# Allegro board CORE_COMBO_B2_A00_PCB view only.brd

Outline 277.73 x 153.4 mm; copper layers: TOP, GND1, IN1, VCC, IN2, IN3, GND2, IN4, GND3, BOTTOM. Coordinates in mm from the lower left corner of the outline.

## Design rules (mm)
net group CRYSTAL: nets PCH_RTCX2 PCH_RTCX2_R
net group DP_AUX_DC: nets DPB_AUX DPB_AUX# DPB_AUX#_C DPB_AUX_C
net group I2C: nets I2C0_SCL_VMM I2C0_SCL_VMM_R I2C0_SDA_VMM I2C0_SDA_VMM_R
net group PCBEEP: nets AUD_PC_BEEP PC_SPKR SPKR
net group PCIE: nets PCIE_PTX_C_DRX_N10 PCIE_PTX_C_DRX_P10 PCIE_PTX_DRX_N10 PCIE_PTX_DRX_P10
net group SMBUS: nets PBAT_SMBCLK PBAT_SMBCLK_C PBAT_SMBDAT PBAT_SMBDAT_C
net group UART: nets ISH_UART0_CTS# ISH_UART0_CTS#_R ISH_UART0_RTS# ISH_UART0_RTS#_R ISH_UART0_RXD ISH_UART0_RXD_R ISH_UART0_TXD ISH_UART0_TXD_R

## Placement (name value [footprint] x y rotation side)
C4  -  [C0402]  151.34 138.72 180 bottom
C7  -  [C1210]  71.18 82.33 270 bottom
C8  -  [C0603]  149.77 137.66 90 bottom
C9  -  [C0402]  83.63 145.02 180 top
C10  -  [NB_C0402_SMALL]  72.02 143.81 180 bottom
C11  -  [NB_C0402_SMALL]  74.56 142.08 180 bottom
C12  -  [NB_C0402_SMALL]  77.96 140.83 0 bottom
C13  -  [NB_C0402_SMALL]  73.71 146.17 270 bottom
C14  -  [NB_C0402_SMALL]  76.25 144.27 270 bottom
C15  -  [NB_C0402_SMALL]  78.85 142.95 270 bottom
C16  -  [NB_C0402_SMALL]  84.49 145.78 180 bottom
C17  -  [NB_C0402_SMALL]  91.32 144.62 90 bottom
C18  -  [NB_C0402_SMALL]  86.8 144.62 90 bottom
C19  -  [C0402]  85.91 140.7 90 top
C20  -  [C0402]  84.9 140.7 90 top
C21  -  [C0402]  88.86 124.91 180 bottom
C22  -  [C0402]  86.46 127.39 0 bottom
C23  -  [VX_C0402_SMALL]  89.19 133.69 90 bottom
C24  -  [VX_C0402_SMALL]  85.07 127.64 90 bottom
C25  -  [C0402]  90.13 133.72 90 bottom
C26  -  [C0402]  83.28 126 270 bottom
C27  -  [C0402]  84.54 125.34 270 bottom
C28  -  [VX_C0402_SMALL]  91.55 130.8 270 bottom
C29  -  [VX_C0402_SMALL]  84.25 127.09 90 bottom
C34  -  [C0402]  76.64 146.42 0 top
C42  -  [NB_C0402_SMALL]  80.2 136.13 90 top
C43  -  [NB_C0402_SMALL]  80.2 134.48 270 top
C50  -  [C0402]  75.25 24.5 270 top
C52  -  [C0603]  54.03 108.99 0 top
C54  -  [C0402]  42.48 96.89 90 bottom
C55  -  [C0402]  43.5 96.89 90 bottom
C56  -  [C0402]  45.65 96.89 90 bottom
C57  -  [C0402]  48.02 98.16 90 bottom
C59  -  [C0402]  44.64 96.89 90 bottom
C60  -  [C0402]  47 98.16 90 bottom
C61  -  [C0402]  40.96 109.85 0 top
C62  -  [C0402]  42.99 104.13 90 top
C63  -  [C0402]  53.4 98.06 180 bottom
C64  -  [C0402]  37.91 102.1 90 top
C65  -  [C0603]  54.03 110.29 0 top
C66  -  [NB_C0402_SMALL]  44.08 108.71 270 top
C68  -  [C0402]  35.24 102.48 180 top
C76  -  [C0402]  155.38 123.18 0 bottom
C85  -  [C0402]  144.21 118.99 0 bottom
C87  -  [C0402]  16.07 119.24 0 bottom
C88  -  [C0603]  15.68 121.28 90 bottom
C103  -  [C0402]  21.27 114.42 0 top
C111  -  [NB_C0402_SMALL]  153.86 61.41 180 bottom
C112  -  [C0402]  153.86 62.42 180 bottom
C113  -  [C0402]  153.1 57.06 180 bottom
C114  -  [C0402]  153.1 58.13 180 bottom
C115  -  [C0402]  38.42 125.59 180 bottom
C117  -  [C0402]  148.17 128.13 0 top
C118  -  [C0603]  45.02 125.64 180 bottom
C119  -  [C0402]  44.97 122.44 180 bottom
C120  -  [C0402]  44.89 124.42 180 bottom
C122  -  [C0603]  48.32 118.1 270 bottom
C123  -  [C0402]  47.05 118.1 270 bottom
C124  -  [NB_C0402_SMALL]  35.12 97.4 90 top
C125  -  [NB_C0402_SMALL]  35.12 94.73 270 top
C128  -  [C0603]  44.51 117.84 270 bottom
C129  -  [C0402]  45.78 118.1 270 bottom
C131  -  [C0603]  36.31 128.4 180 top
C133  -  [C0402]  47.2 125.59 0 top
C134  -  [C0402]  35.62 118.48 180 top
C135  -  [C0402]  51.5 121.53 180 top
C136  -  [NB_C0402_SMALL]  51.5 122.8 180 top
C137  -  [C0402]  34.44 131.18 180 bottom
C139  -  [NB_C0402_SMALL]  48.83 120.64 180 top
C143  -  [C0402]  47.2 126.73 0 top
C147  -  [NB_C0402_SMALL]  47.98 130.52 0 bottom
C148  -  [NB_C0402_SMALL]  47.98 129.38 0 bottom
C149  -  [C0402]  50.07 126.66 0 bottom
C150  -  [C0603]  37.76 120.1 180 bottom
C151  -  [C0402]  50.76 131.89 0 bottom
C155  -  [C0402]  87.98 140.3 90 top
C156  -  [C0402]  86.96 140.3 90 top
C157  -  [C0402]  89.22 138.29 90 top
C158  -  [C0402]  88.2 138.29 90 top
C159  -  [C0402]  91.59 138.29 90 top
C160  -  [C0402]  90.57 138.29 90 top
C161  -  [C0402]  94.49 137.62 0 top
C162  -  [C0402]  94.49 136.6 0 top
C176  -  [C0402]  139.36 134.05 180 top
C178  -  [C0402]  139.36 132.91 180 top
C179  -  [C0402]  139.36 135.07 180 top
C180  -  [C0603]  139.25 129.78 180 top
C181  -  [C0402]  139.36 131.89 180 top
C182  -  [C0402]  145.48 132.7 180 bottom
C183  -  [C0402]  147.76 134.23 180 bottom
C184  -  [C0402]  142.17 133.59 180 bottom
C185  -  [C0402]  142.17 134.74 180 bottom
C186  -  [C0402]  144.08 134.74 0 bottom
C187  -  [C0805]  140.65 137.76 180 top
C188  -  [C0805]  149.29 131.06 90 bottom
C189  -  [C0402]  144.46 125.72 0 top
C190  -  [C0402]  146.72 125.77 0 top
C191  -  [C0402]  21.27 115.56 0 top
C198  -  [C0402]  162.39 139.08 270 top
C199  -  [C0402]  21.27 117.08 0 top
C208  -  [C0402]  174.41 34.81 270 bottom
C209  -  [C0402]  21.27 118.23 0 top
C242  -  [C0402]  22.29 128 0 bottom
C243  -  [C0402]  22.29 129.02 0 bottom
C248  -  [NB_C0402_SMALL]  99.05 121.48 270 bottom
C249  -  [NB_C0402_SMALL]  99.12 141.09 90 bottom
C250  -  [C0402]  98.03 121.48 270 bottom
C251  -  [C0805]  98.62 137.15 270 bottom
C252  -  [C0402]  96.33 141.09 90 bottom
C253  -  [C7343D_H75]  92.52 121.78 0 bottom
C254  -  [C7343D_H75]  92.64 137.63 0 bottom
C257  -  [C0402]  31.18 114.93 180 bottom
C258  -  [NB_C0402_SMALL]  31.18 116.07 180 bottom
C259  -  [NB_C0402_SMALL]  31.94 135.88 0 top
C260  -  [C0402]  31.94 133.72 0 top
C261  -  [C0402]  31.94 134.86 0 top
C262  -  [C0603]  33.59 114.93 0 bottom
C263  -  [C0402]  15.17 140.83 0 top
C266  -  [C0402]  13.65 138.55 0 top
C269  -  [C0402]  21.27 111.88 0 top
C270  -  [C0402]  21.27 113.02 0 top
C271  -  [C0402]  21.27 109.46 0 top
C272  -  [C0402]  21.27 110.61 0 top
C288  -  [C0603]  27.93 97.71 90 top
C289  -  [C0402]  26.74 97.91 90 top
C290  -  [C7343D_H75]  21.52 100.45 180 top
C291  -  [C0402]  17.59 97.4 0 top
C292  -  [C0402]  24.88 95.7 0 top
C293  -  [C0402]  24.88 96.71 0 top
C328  -  [C0603]  271.54 51.5 0 top
C329  -  [C0402]  268.29 55.23 0 top
C330  -  [C0402]  252.39 53.71 180 top
C331  -  [C0402]  256.47 45.58 270 top
C332  -  [C0402]  259.01 61.84 90 top
C333  -  [C0402]  17.84 125.09 180 bottom
C334  -  [C0402]  267.52 48.76 270 top
C336  -  [C0603]  257.74 62.22 90 top
C337  -  [NB_C0402_SMALL]  252.54 58.28 180 top
C339  -  [C0402]  270.19 54.09 0 top
C340  -  [C0402]  225.88 47.42 270 top
C342  -  [C0402]  224.85 47.74 90 top
C343  -  [C0402]  227.62 49.24 0 top
C344  -  [C0402]  225.88 49.95 270 top
C345  -  [C0402]  222.13 51.35 0 top
C346  -  [C0402]  242.05 55.77 0 top
C347  -  [C0402]  222.69 58.61 180 top
C348  -  [C0603]  241.29 68.31 90 top
C349  -  [C0402]  232.98 64.39 90 top
C350  -  [C0402]  241.87 63.36 0 top
C351  -  [C0402]  242 58.03 0 top
C352  -  [C0402]  242.05 54.62 0 top
C353  -  [C0402]  225.11 57.52 180 top
C354  -  [C0402]  229.65 49.24 180 top
C355  -  [C0402]  241.23 48.3 0 top
C356  -  [C0402]  225.23 60.44 180 top
C358  -  [NB_C0402_SMALL]  239.58 49.26 0 top
C359  -  [NB_C0402_SMALL]  241.23 49.26 0 top
C360  -  [C0402]  226.5 62.85 180 top
C361  -  [NB_C0402_SMALL]  240.47 51.93 270 top
C362  -  [C0402]  231.71 64.39 90 top
C363  -  [NB_C0402_SMALL]  245.04 60.31 0 top
C364  -  [C0402]  226.25 53.96 90 top
C365  -  [C0402]  226.25 51.93 270 top
C366  -  [C0603]  244.71 53.71 0 top
C367  -  [C0402]  241.84 52.11 0 top
C368  -  [NB_C0402_SMALL]  245.68 37.45 90 top
C369  -  [NB_C0402_SMALL]  243.52 48.93 270 top
C370  -  [NB_C0402_SMALL]  156.4 106.03 90 bottom
C371  -  [C0402]  242.12 61.33 270 top
C373  -  [NB_C0402_SMALL]  199.5 25.21 90 bottom
C374  -  [C0402]  144.33 63.91 0 top
C375  -  [C0402]  144.46 51.14 180 top
C376  -  [C0402]  144.46 50.03 180 top
C377  -  [NB_C0402_SMALL]  150.38 61.2 270 top
C378  -  [NB_C0402_SMALL]  150.38 64.12 90 top
C379  -  [NB_C0402_SMALL]  148.22 62.04 270 top
C380  -  [NB_C0402_SMALL]  148.22 63.69 90 top
C385  -  [C0603]  38.39 122.62 90 bottom
C389  -  [C0402]  182.43 89.9 180 top
C390  -  [NB_C0402_SMALL]  181.67 90.92 180 top
C391  -  [NB_C0402_SMALL]  181.54 97.91 180 top
C393  -  [C0402]  182.43 98.92 0 top
C395  -  [NB_C0402_SMALL]  227.32 64.5 270 top
C396  -  [C0402]  182.43 95.87 180 top
C397  -  [NB_C0402_SMALL]  181.54 97.02 180 top
C398  -  [NB_C0402_SMALL]  207.22 64.12 90 top
C399  -  [C0402]  206.03 63.46 270 top
C400  -  [C0402]  181.87 85.76 0 top
C401  -  [NB_C0402_SMALL]  181.67 87.62 180 top
C402  -  [NB_C0402_SMALL]  208.11 64.12 90 top
C403  -  [C0402]  209.1 63.36 270 top
C409  -  [NB_C0402_SMALL]  54.47 117.92 180 bottom
C410  -  [C0402]  44.97 117.49 270 top
C413  -  [NB_C0402_SMALL]  199.58 40.63 90 bottom
C422  -  [C0402]  53.78 120.51 90 bottom
C425  -  [C0402]  58.1 117.97 90 bottom
C426  -  [C0402]  184.47 136.01 270 top
C427  -  [NB_C0402_SMALL]  55.94 117.72 270 bottom
C430  -  [C0402]  199.07 39.28 0 bottom
C431  -  [NB_C0603_H34_SMALL]  53.53 96.87 0 bottom
C440  -  [C0402]  36.38 109.84 180 top
C452  -  [C0402]  184.47 138.93 90 top
C633  -  [C0402]  187.77 54.98 270 bottom
C634  -  [C0402]  189.29 54.98 270 bottom
C635  -  [C0402]  186.62 54.98 270 bottom
C645  -  [C0402]  194.78 56.71 90 bottom
C647  -  [C0402]  171.26 57.01 180 bottom
C648  -  [C0402]  171.26 56 180 bottom
C809  -  [C7343D_H75]  21.52 100.83 180 bottom
C1002  -  [C0402]  259.27 5.2 90 top
C1103  -  [C0402]  137.43 110.13 270 top
C1104  -  [C0402]  136.41 110.13 270 top
C1186  -  [C0402]  181.47 106.97 0 top
C1187  -  [C0402]  258.89 8.88 90 top
C1189  -  [C0402]  115.63 65.14 180 top
C2750  -  [NB_C0402_SMALL]  51.5 123.76 0 top
C2800  -  [C0402]  164.63 125.32 180 bottom
C2801  -  [C0402]  164.63 124.3 180 bottom
C2802  -  [C0402]  168.26 122.8 180 top
C2803  -  [C0402]  164.63 123.27 180 bottom
C2805  -  [C1808]  164.12 129.39 90 bottom
C3004  -  [NB_C0402_SMALL]  199.1 36.64 0 bottom
C3005  -  [C0402]  199.07 38.24 0 bottom
C3050  -  [C0402]  185.86 128.89 90 top
C3051  -  [C0402]  184.47 133.47 270 top
C3052  -  [C0603]  184.47 129.15 90 top
C3053  -  [C0603]  182.05 121.02 270 top
C3054  -  [C0402]  182.69 125.97 180 top
C3055  -  [C0402]  182.81 131.18 0 top
C3056  -  [C0402]  187.01 131.18 180 top
C3057  -  [C0402]  182.56 133.34 270 top
C3058  -  [C0402]  185.61 133.47 270 top
C3059  -  [C0402]  186.24 136.39 90 bottom
C3060  -  [C0402]  185.1 136.39 90 bottom
C3061  -  [C0402]  181.98 122.8 180 bottom
C3062  -  [C0402]  181.98 124.98 180 bottom
C3063  -  [C0402]  189.29 129.02 270 bottom
C3079  -  [C0402]  175.45 54.6 0 top
C3080  -  [NB_C3528_H79]  152.26 134.48 90 bottom
C3082  -  [C0402]  181.42 103.62 0 top
C3083  -  [C0402]  181.14 129.53 270 top
C3084  -  [VX_C0402_SMALL]  86.8 125.95 180 bottom
C3085  -  [C0402]  89.22 127.46 270 bottom
C3086  -  [C0402]  86.5 130.01 180 bottom
C3087  -  [C0402]  91.17 133.72 90 bottom
C3088  -  [VX_C0402_SMALL]  84.39 130.93 90 bottom
C3091  -  [VX_C0402_SMALL]  84.39 129.27 270 bottom
C3092  -  [C0402]  83.37 129.15 270 bottom
C3093  -  [VX_C0402_SMALL]  86.42 128.71 180 bottom
C3094  -  [VX_C0402_SMALL]  89.57 130.27 90 bottom
C3401  -  [C0603]  139 137.66 90 bottom
C3402  -  [C0402]  140.27 137.78 90 bottom
C3601  -  [C0402]  205.3 150.36 90 top
C3602  -  [C0402]  207.84 148.33 180 top
C3603  -  [C0402]  211.01 141.47 180 top
C3701  -  [C0402]  263.41 39.64 90 top
C7106  -  [NB_C0402_SMALL]  245.27 99.43 0 bottom
C7108  -  [NB_C0402_SMALL]  240.35 105.07 180 bottom
C7109  -  [NB_C0402_SMALL]  240.93 107.61 180 bottom
C7110  -  [NB_C0402_SMALL]  244.13 111.36 270 bottom
C7111  -  [NB_C0402_SMALL]  248.47 110.5 90 bottom
C7112  -  [NB_C0402_SMALL]  245.27 98.36 0 bottom
C9207  -  [C0402]  174.71 42.81 0 bottom
C9430  -  [NB_R0402_SMALL]  49.09 93.89 90 bottom
C9432  -  [C0603]  38.42 127.11 180 bottom
C9433  -  [VX_C0402_SMALL]  265.87 39.26 180 top
C9437  -  [C0402]  261.28 41.95 180 top
C9438  -  [C0603]  137.4 138.19 90 bottom
C9439  -  [C0603]  136.08 138.19 90 bottom
C9440  -  [C0603]  128.31 134.71 180 bottom
C9441  -  [C0402]  118.81 146.93 90 bottom
C9442  -  [C0402]  122.24 146.93 90 bottom
C9443  -  [C0402]  119.95 146.93 90 bottom
C9444  -  [C0402]  121.09 146.93 90 bottom
C9445  -  [C0402]  259.65 26.66 180 top
C9446  -  [C0402]  259.65 25.52 180 top
C9447  -  [C0402]  262.37 39.64 90 top
C9448  -  [C0402]  270.7 34.53 0 top
C9449  -  [C0402]  270.57 31.87 0 top
C9450  -  [C0402]  257.24 30.98 270 top
C9451  -  [C0402]  261.33 39.64 90 top
C9453  -  [C0603]  133.16 143.12 0 top
C9454  -  [C0603]  130.11 146.17 0 top
C9455  -  [NB_C0402_SMALL]  132.14 137.78 90 top
C9456  -  [C0603]  134.02 138.29 0 top
C9457  -  [C0402]  153.45 103.26 270 bottom
C9458  -  [C0402]  155.26 102.86 180 bottom
C9459  -  [C0402]  155.13 98.29 180 bottom
C9460  -  [NB_C0402_SMALL]  237.93 49.26 180 top
C9461  -  [NB_C0402_SMALL]  157.67 68.19 90 bottom
C9462  -  [C0402]  159.07 129.78 180 bottom
C9463  -  [C0402]  193.74 56.71 90 bottom
C9464  -  [C0402]  117.66 146.93 90 bottom
C9491  -  [C0402]  244.41 59.3 180 top
C9492  -  [NB_C0402_SMALL]  175.42 34.97 90 bottom
C9493  -  [NB_C0402_SMALL]  175.58 49.39 0 top
C9494  -  [NB_C0402_SMALL]  175.58 51.68 0 top
C9495  -  [NB_C0402_SMALL]  175.58 52.57 0 top
C9505  -  [NB_C0402_SMALL]  183.07 137.53 270 top
C9506  -  [NB_C0402_SMALL]  159.19 129.27 180 top
C9507  -  [NB_C0402_SMALL]  161.86 136.51 90 top
C9508  -  [NB_C0402_SMALL]  35.37 100.57 0 top
C9509  -  [NB_C0402_SMALL]  43.24 101.46 0 top
C9510  -  [NB_C0402_SMALL]  54.16 107.09 0 top
C9511  -  [NB_C0402_SMALL]  53.58 99 180 bottom
C9512  -  [NB_C0402_SMALL]  41.09 101.46 0 top
C9513  -  [NB_C0402_SMALL]  12.89 141.09 90 top
C9514  -  [NB_C0402_SMALL]  13.78 141.09 90 top
C9515  -  [C0402]  40.96 130.57 270 top
C9516  -  [C0402]  39.38 130.8 270 top
C9525  -  [C0402]  15.3 115.31 270 bottom
C9526  -  [C0402]  16.45 115.31 270 bottom
C9527  -  [C0402]  16.42 117.72 270 bottom
C9528  -  [C0402]  15.3 117.72 270 bottom
C9539  -  [NB_C0402_SMALL]  94.96 110.2 90 bottom
C9540  -  [NB_C0402_SMALL]  92.37 110.2 90 bottom
C9541  -  [NB_C0402_SMALL]  89.88 110.2 90 bottom
C9542  -  [NB_C0402_SMALL]  94.07 110.2 270 bottom
C9543  -  [NB_C0402_SMALL]  93.2 110.2 270 bottom
C9544  -  [NB_C0402_SMALL]  90.71 110.2 270 bottom
C9548  -  [C0402]  130.31 109.72 270 bottom
C9549  -  [C0402]  131.38 109.72 270 bottom
C9550  -  [C0402]  132.14 115.43 270 bottom
C9551  -  [C0402]  131 115.43 270 bottom
C9552  -  [C0402]  163.23 53.2 180 top
C9553  -  [VX_C0402_SMALL]  169.05 48.78 90 top
C9554  -  [VX_C0402_SMALL]  167.57 61.53 180 top
C9555  -  [C0402]  163.16 64.17 180 top
C9556  -  [C0402]  181.42 101.46 0 top
C9557  -  [C0402]  181.42 102.53 0 top
C9558  -  [C0603]  181.44 104.82 0 top
C9559  -  [C0402]  159.37 122.09 90 bottom
C9560  -  [C0402]  152.33 118.73 270 bottom
C9562  -  [C0402]  187.67 149.7 90 bottom
C9563  -  [C0603]  188.93 149.99 90 bottom
C9564  -  [C0402]  187.23 141.24 270 bottom
C9565  -  [C0603]  194.93 143.07 0 bottom
C9566  -  [C0402]  194.75 144.26 0 bottom
C9567  -  [C0402]  192.21 149.98 90 bottom
C9568  -  [C0402]  193.76 47.61 270 bottom
C9569  -  [C0603]  194.98 47.71 270 bottom
C9606  -  [C0603]  120.33 70.6 270 top
C9607  -  [C0402]  121.52 70.45 270 top
C9608  -  [C0402]  122.75 110.04 270 bottom
C9609  -  [C0402]  123.77 112.3 90 bottom
C9610  -  [C0402]  115.89 68.39 180 top
C9611  -  [C0402]  122.75 111.94 90 bottom
C9612  -  [C0402]  117.71 73.75 270 top
C9613  -  [C0603]  107.5 72.79 180 top
C9614  -  [C0603]  107.5 74.11 180 top
C9615  -  [C0402]  107.5 71.26 180 top
C9616  -  [C0402]  115.28 74.69 0 top
C9617  -  [C0402]  118.86 73.75 270 top
C9618  -  [C0603]  115.17 73.52 0 top
C9619  -  [C0805]  94.42 50.28 180 top
C9620  -  [C0603]  115.17 72.22 0 top
C9621  -  [C0603]  115.17 70.9 0 top
C9622  -  [C0603]  115.17 69.58 0 top
C9623  -  [C0805]  96.84 76.44 0 top
C9624  -  [C0805]  95.82 53.46 180 top
C9625  -  [C0402]  127.57 90.11 0 top
C9626  -  [C0402]  124.27 92.83 180 top
C9627  -  [C0402]  137.81 88.86 90 top
C9628  -  [C0402]  142.61 110.25 90 bottom
C9629  -  [C0805]  153.81 110.45 270 top
C9630  -  [C0402]  155.36 110.94 270 top
C9631  -  [C0402]  131.89 98.03 90 top
C9632  -  [C0805]  153.6 107.35 180 top
C9633  -  [C0402]  129.22 95.24 180 top
C9634  -  [C0402]  125.03 91.78 180 top
C9635  -  [C0402]  124.27 93.85 180 top
C9636  -  [C0402]  126.3 95.87 180 top
C9637  -  [C0402]  127.57 92.7 0 top
C9638  -  [C0402]  131.71 88.63 270 top
C9639  -  [C0402]  129.45 90.11 180 top
C9640  -  [C0402]  137.98 97.27 0 top
C9641  -  [C0402]  143.83 91.63 0 bottom
C9642  -  [C0402]  134.02 68.21 270 top
C9643  -  [C0402]  132.98 68.21 270 top
C9644  -  [C0402]  130.11 76.19 180 top
C9645  -  [C0402]  130.11 75.05 180 top
C9647  -  [C0805]  146.39 111.37 270 top
C9648  -  [C0805]  142.31 111.37 270 top
C9649  -  [C0805]  144.35 111.37 270 top
C9650  -  [C0402]  133.08 109.39 270 bottom
C9653  -  [C0402]  157.39 101.08 90 top
C9654  -  [C0603]  154.96 97.04 90 top
C9655  -  [C0603]  157.02 96.41 0 top
C9656  -  [C0805]  140.27 111.37 270 top
C9657  -  [C0402]  122.74 88.53 0 top
C9658  -  [C0402]  120.86 89.57 180 top
C9659  -  [C0402]  120.86 88.53 180 top
C9660  -  [C0402]  113.02 90.49 180 top
C9663  -  [C0402]  113.02 89.42 180 top
C9664  -  [C0402]  113.02 88.38 180 top
C9665  -  [C0402]  122.74 89.57 0 top
C9666  -  [C0402]  122.62 91.05 90 top
C9840  -  [NB_C0402_SMALL]  181.67 86.73 180 top
C9841  -  [NB_C0402_SMALL]  181.67 91.81 180 top
C9842  -  [C0402]  182.74 88.84 0 top
C9843  -  [C0402]  182.43 92.95 0 top
C9851  -  [C0402]  93.35 111.11 270 top
C9855  -  [C0402]  135.38 141.84 0 top
C9856  -  [C0402]  83.37 131.05 90 bottom
C9884  -  [C0402]  139.89 75.43 90 bottom
C9885  -  [C0402]  174.13 122.77 270 top
C9886  -  [C0402]  172.38 65.9 180 top
C9887  -  [C0402]  135.93 109.51 90 bottom
C9888  -  [C0603]  111.39 89.14 90 top
C9889  -  [C0603]  110.11 89.14 90 top
C9897  -  [C0603]  38.21 131.28 90 top
C9898  -  [C0603]  36.64 118.4 180 bottom
C9899  -  [C0603]  46.55 122.42 90 top
C9900  -  [C0402]  35.62 119.62 180 top
C9901  -  [C0603]  35.93 126.58 180 top
C9903  -  [C0402]  38.01 118.43 180 top
C9904  -  [C0603]  37.96 116.98 180 bottom
C9905  -  [C0402]  181.11 109.51 0 top
C9906  -  [C0402]  94.73 119.14 90 top
C9907  -  [NB_C0402_SMALL]  43.24 102.35 0 top
C9908  -  [NB_C0402_SMALL]  35.37 101.46 180 top
C9909  -  [NB_C0402_SMALL]  53.91 99.94 180 bottom
C9910  -  [NB_C0402_SMALL]  54.16 107.93 0 top
C9911  -  [NB_C0402_SMALL]  41.09 102.35 0 top
C9912  -  [NB_C0402_SMALL]  55.81 98.67 270 bottom
C9913  -  [NB_C0402_SMALL]  83.63 145.99 180 top
C9914  -  [NB_C0402_SMALL]  82.23 135.73 90 bottom
C9915  -  [NB_C0402_SMALL]  82.1 130.67 180 top
C9916  -  [NB_C0402_SMALL]  82.1 129.3 180 top
C9917  -  [NB_C0402_SMALL]  82.1 128.26 180 top
C9918  -  [C0402]  162.85 120.66 0 bottom
C9919  -  [C0402]  171.03 42.53 90 bottom
C9920  -  [C0402]  172.65 42.79 180 bottom
C9921  -  [C0402]  170.75 35.19 0 bottom
C9922  -  [C0402]  173.26 34.81 270 bottom
C9923  -  [NB_C0402_SMALL]  183.07 135.88 270 top
C9924  -  [NB_C0402_SMALL]  193.64 141.29 270 bottom
C9925  -  [NB_C0402_SMALL]  181.42 105.93 0 top
C9926  -  [NB_C0402_SMALL]  175.58 53.46 0 top
C9927  -  [NB_C0402_SMALL]  181.16 108.55 0 top
C9928  -  [NB_C0402_SMALL]  181.47 100.47 0 top
C9929  -  [C0402]  73.59 30.09 180 top
C9930  -  [C0603]  153.55 73.65 180 bottom
C9931  -  [C0402]  155.26 101.79 180 bottom
C9941  -  [NB_C0402_SMALL]  259.14 39.46 90 top
C9942  -  [C0402]  145.48 131.56 180 bottom
C9943  -  [C0402]  86.17 134.02 180 bottom
C9944  -  [VX_C0402_SMALL]  87.92 133.9 0 bottom
C9945  -  [VX_C0402_SMALL]  87.92 134.74 0 bottom
C9946  -  [C0402]  86.17 135.12 180 bottom
C9947  -  [C0402]  86.93 124.93 180 bottom
C9948  -  [C0402]  155.27 91.63 180 bottom
C9949  -  [C0402]  155.27 90.62 180 bottom
C9950  -  [C0402]  88.58 114.29 0 top
C9952  -  [C0603]  148.4 137.66 90 bottom
C9953  -  [C0402]  269.23 45.28 0 top
C9954  -  [C0402]  271.41 46.11 90 top
C9955  -  [C0402]  272.55 37.2 270 top
C9956  -  [C0603]  269.34 46.44 0 top
C9957  -  [C0402]  272.35 49.01 0 top
C9958  -  [C0603]  138.67 75.36 90 bottom
C9959  -  [C0402]  129.73 92.7 180 top
C9960  -  [C0402]  127.39 88.58 0 top
C9961  -  [NB_C0402_SMALL]  161.22 111.62 270 top
C9962  -  [C0402]  162.37 111.62 270 top
C9963  -  [NB_C0402_SMALL]  130.69 127.32 270 bottom
C9964  -  [NB_C0402_SMALL]  131.61 127.32 270 bottom
C9965  -  [NB_C0402_SMALL]  188.4 28.74 270 top
C9966  -  [C0402]  189.42 28.82 270 top
C9967  -  [NB_C0402_SMALL]  185.1 85.1 180 top
C9968  -  [C0402]  190.76 84.82 0 top
C9969  -  [NB_C0402_SMALL]  74.36 89.4 270 bottom
C9970  -  [C0402]  76.01 89.27 270 bottom
C9971  -  [NB_C0402_SMALL]  69.66 85.71 0 bottom
C9972  -  [C0402]  69.66 87.24 0 bottom
C9973  -  [NB_C0402_SMALL]  107.53 122.19 180 top
C9974  -  [C0402]  107.53 123.18 180 top
C9975  -  [NB_C0402_SMALL]  118.37 116.42 0 bottom
C9976  -  [C0402]  118.4 117.67 0 bottom
C9977  -  [NB_C0402_SMALL]  114.74 128.13 270 bottom
C9978  -  [C0402]  117.66 128.26 270 bottom
C9979  -  [NB_C0402_SMALL]  98.23 141.09 90 bottom
C9980  -  [NB_C0402_SMALL]  97.34 141.09 90 bottom
C9981  -  [C0603]  193.69 149.92 90 bottom
C9982  -  [C0402]  249.26 47.54 90 top
C9983  -  [C0402]  121.96 65.93 270 top
C9984  -  [C0402]  115.9 67.35 180 top
C9985  -  [C0402]  123.12 64.45 180 top
C9986  -  [NB_C0402_SMALL]  50.86 97.15 270 bottom
CC5  -  [C0402]  130.9 66.87 90 top
CC6  -  [NB_C0402_SMALL]  120.23 110.5 0 bottom
CC7  -  [NB_C0402_SMALL]  117.94 110.5 180 bottom
CC10  -  [C0402]  79.36 114.49 180 bottom
CC11  -  [C0402]  79.36 113.45 180 bottom
CC24  -  [C0402]  132.8 88.63 90 top
CC25  -  [C0402]  130.67 71.31 90 top
CC26  -  [C0402]  135.82 88.63 0 top
CC41  -  [C0402]  60.89 115.74 180 bottom
CC57  -  [C0402]  126.05 70.85 180 top
CC67  -  [C0402]  132.65 39.11 0 top
CC69  -  [C0402]  133.67 25.77 0 top
CC80  -  [C0402]  128.71 71.24 90 top
CC89  -  [NB_C0402_SMALL]  184.41 125.21 180 bottom
CC90  -  [NB_C0402_SMALL]  186.19 125.21 0 bottom
CC91  -  [NB_C0402_SMALL]  144.11 76.01 0 bottom
CC92  -  [NB_C0402_SMALL]  145.22 74.44 0 bottom
CC93  -  [C0402]  82.74 114.29 270 bottom
CC94  -  [C0402]  157.67 89.14 90 top
CC266  -  [VX_C0402_SMALL]  157.26 92.7 90 top
CC267  -  [C0402]  133.67 75.17 270 bottom
CC268  -  [C0402]  79.92 125.51 0 bottom
CC269  -  [C0402]  131.79 92.52 0 top
CC270  -  [NB_C0402_SMALL]  90.99 102.22 0 bottom
CC271  -  [NB_C0402_SMALL]  93.03 103.11 0 bottom
CC272  -  [C0402]  75.37 127.12 270 bottom
CC273  -  [C0402]  81.67 114.29 270 bottom
CC275  -  [NB_C0402_SMALL]  153.38 94.98 180 bottom
CC276  -  [NB_C0402_SMALL]  138.82 111.49 180 bottom
CC277  -  [NB_C0402_SMALL]  129.09 76.01 270 bottom
CC278  -  [NB_C0402_SMALL]  138.74 111.11 90 top
CC279  -  [NB_C0402_SMALL]  125.28 73.52 90 top
CC280  -  [NB_C0402_SMALL]  128.2 76.01 270 bottom
CC281  -  [NB_C0402_SMALL]  252.41 52.69 0 top
CC282  -  [NB_C0402_SMALL]  255.46 45.71 90 top
CC284  -  [NB_C0402_SMALL]  244.41 56 180 top
CC285  -  [NB_C0402_SMALL]  238.44 67.17 90 top
CC286  -  [NB_C0402_SMALL]  230.77 64.5 270 top
CC287  -  [C0402]  130.9 64.71 90 top
CC288  -  [NB_C0402_SMALL]  137.04 109.36 270 bottom
CC289  -  [C0402]  130.67 69.33 90 top
CC290  -  [C0402]  127.57 71.24 90 top
CD3  -  [C0402]  106.61 39.1 180 top
CD4  -  [C0402]  110.3 47.23 90 top
CD5  -  [C0402]  123.25 47.23 90 top
CD6  -  [C0402]  119.94 47.23 90 top
CD7  -  [C0402]  122.11 47.23 90 top
CD8  -  [C0402]  113.85 47.23 90 top
CD9  -  [C0402]  98.23 38.49 270 top
CD10  -  [C0402]  120.97 47.23 90 top
CD11  -  [C0402]  112.71 47.23 90 top
CD12  -  [C0603]  127.96 38.48 270 top
CD13  -  [C0402]  126.81 38.48 270 top
CD14  -  [C0603]  120.71 38.47 270 top
CD15  -  [C0603]  112.37 38.34 270 top
CD16  -  [C0603]  116.39 38.47 270 top
CD17  -  [C0603]  113.67 38.34 270 top
CD18  -  [C0603]  122.11 38.47 270 top
CD19  -  [C0603]  111.04 38.34 270 top
CD20  -  [C0603]  117.92 38.47 270 top
CD21  -  [C0603]  109.72 38.34 270 top
CD22  -  [VX_C7343D_H79]  96.07 59.17 90 top
CD23  -  [C0402]  83.5 33.26 90 top
CD24  -  [C0402]  145.35 46.9 270 top
CD25  -  [C0603]  143.57 38.98 0 top
CD26  -  [C0402]  146.8 40.89 90 top
CD27  -  [C0402]  145.73 40.89 90 top
CD28  -  [C0402]  147.83 40.89 90 top
CD29  -  [C0402]  144.71 40.89 90 top
CD30  -  [C0603]  146.37 38.47 270 top
CD31  -  [C0603]  147.76 38.47 270 top
CD34  -  [C0402]  106.74 26.4 270 top
CD36  -  [C0402]  104.46 26.66 270 top
CD37  -  [C0402]  115.25 25.01 270 top
CD38  -  [C0402]  84.92 25.75 0 top
CD39  -  [C0402]  121.25 25.26 270 top
CD40  -  [C0402]  113.98 33.68 90 top
CD41  -  [C0402]  116.93 47.23 90 top
CD42  -  [C0402]  110.93 33.64 90 top
CD43  -  [C0402]  137.7 25.29 270 top
CD45  -  [C0603]  109.03 25.14 270 top
CD46  -  [C0603]  115.38 33.64 90 top
CD47  -  [C0603]  119.62 33.66 90 top
CD48  -  [C0603]  110.47 25.13 270 top
CD49  -  [C0603]  116.52 25.14 270 top
CD50  -  [C0603]  112.46 33.64 90 top
CD51  -  [C0603]  122.9 33.66 90 top
CD52  -  [C0603]  120.08 25.14 270 top
CD53  -  [VX_C7343D_H79]  129.09 33.79 180 top
CD54  -  [C0402]  146.29 25.03 90 top
CD55  -  [C0402]  144 25.03 90 top
CD56  -  [C0402]  147.43 25.03 90 top
CD57  -  [C0402]  145.15 25.03 90 top
CD58  -  [C0603]  141.34 25.01 90 top
CD59  -  [C0603]  142.76 25.01 90 top
CD60  -  [C0402]  125.28 25.77 90 top
CD61  -  [C0603]  126.68 25.13 90 top
CD62  -  [C0402]  121.47 33.68 90 top
CD63  -  [C0402]  107.76 76.29 180 top
CD64  -  [C0402]  98.49 46.85 90 top
CD65  -  [C0402]  103.95 38.72 270 top
CD66  -  [C0402]  97.34 46.85 90 top
CD67  -  [C0402]  143.11 46.75 270 top
CD68  -  [C0402]  90.99 46.6 90 top
CD69  -  [C0402]  99.63 46.85 90 top
CD70  -  [C0402]  142.07 46.75 270 top
CD71  -  [C0603]  98.74 49.9 270 top
CD72  -  [C0603]  108.39 38.34 270 top
CD73  -  [C0603]  113.6 25.13 270 top
CD74  -  [C0603]  108.77 34.15 0 top
CD75  -  [C0603]  123.5 38.47 270 top
CD76  -  [C0603]  111.95 28.06 90 top
CD77  -  [C0603]  97.34 49.9 270 top
CD78  -  [C0603]  119.31 38.47 270 top
CD85  -  [C0402]  147.05 45.86 180 top
CD86  -  [C0402]  147.05 44.72 180 top
CD89  -  [C0603]  150.05 39.23 180 top
CD90  -  [C0603]  150.05 37.84 180 top
CD93  -  [C0402]  93.46 25.67 180 top
CD95  -  [C0402]  84.01 38.47 270 top
CD96  -  [C0402]  99.69 33.13 0 top
CD97  -  [C0402]  137.98 38.47 270 top
CD98  -  [C0402]  143.19 33.52 90 top
CD99  -  [C0402]  90.1 32.88 0 top
CD100  -  [C0402]  94.02 38.42 270 top
CD101  -  [C0603]  138.62 33.39 90 top
CD102  -  [C0603]  138.88 25.31 270 top
CD103  -  [C0603]  108.77 32.75 0 top
CD104  -  [C0603]  118.22 33.64 90 top
CD105  -  [C0603]  116.9 33.64 90 top
CD106  -  [C0603]  135.44 27.8 270 top
CD107  -  [C0603]  102.68 38.47 270 top
CD108  -  [C0603]  108.77 35.47 0 top
CD132  -  [C0402]  146.24 33.39 90 top
CD133  -  [C0603]  146.37 31.23 0 top
CD134  -  [C0402]  148.52 33.39 270 top
CD135  -  [C0402]  147.38 33.39 270 top
CD136  -  [C0603]  149.79 33.2 270 top
CD137  -  [C0603]  151.19 33.2 270 top
CE1  -  [NB_C0402_SMALL]  33.72 101.34 90 top
CE2  -  [NB_C0402_SMALL]  32.83 101.34 90 top
CE14  -  [C0402]  172.38 67.04 180 top
CE22  -  [C0402]  171.26 54.85 180 bottom
CMOS1  -  [NB_OPEN2_5MIL_PT]  139.63 66.41 270 bottom
CRTF1  -  [POLYSWITCH_2P_179X128_POLY]  88.1 144.44 180 top
CS1  -  [VX_C0402_SMALL]  191.2 39.87 270 bottom
CS2  -  [VX_C0402_SMALL]  192.01 39.87 270 bottom
CS3  -  [VX_C0402_SMALL]  193.1 39.87 270 bottom
CS4  -  [VX_C0402_SMALL]  193.91 39.87 270 bottom
CU16  -  [C0402]  114.95 138.11 270 top
CU17  -  [C0402]  113.93 138.11 270 top
CU18  -  [C0402]  112.81 138.11 270 top
CU19  -  [C0402]  111.8 138.11 270 top
CU20  -  [C0402]  118.32 138.11 270 top
CU21  -  [C0402]  119.34 138.11 270 top
CU22  -  [C0402]  116.08 138.11 270 top
CU23  -  [C0402]  117.09 138.11 270 top
CU31  -  [C0402]  165.54 65.9 270 bottom
CU32  -  [C0402]  166.56 65.9 270 bottom
CU33  -  [C0402]  167.83 65.9 270 bottom
CU34  -  [C0402]  168.84 65.9 270 bottom
CU35  -  [C0402]  165.29 57.65 270 bottom
CU36  -  [C0402]  166.3 57.65 270 bottom
CU41  -  [C0402]  165.29 54.34 270 bottom
CU42  -  [C0402]  166.3 54.34 270 bottom
CU43  -  [C0402]  167.7 54.34 270 bottom
CU44  -  [C0402]  168.72 54.34 270 bottom
CU45  -  [C0402]  165.42 45.96 270 bottom
CU46  -  [C0402]  166.43 45.96 270 bottom
CU47  -  [C0402]  167.57 45.96 270 bottom
CU48  -  [C0402]  168.72 45.96 270 bottom
CU49  -  [C0402]  168.72 57.65 270 bottom
CU50  -  [C0402]  167.7 57.65 270 bottom
CZ58  -  [C0402]  107.12 132.83 0 top
CZ59  -  [C0402]  107.12 133.85 0 top
D1  -  [SOD523]  71.44 78.86 180 bottom
D2  -  [SOT323_ONSEMI]  55.94 91.83 180 bottom
D4  -  [SOT23_S6_FITI_H51]  89.13 142.74 0 bottom
D12  -  [SOD523]  28.77 122.53 0 top
D14  -  [SOD523]  28.77 124.07 0 top
D17  -  [DFN_9P_34_39X98_AMA]  17.69 95.11 0 top
D21  -  [SOT323_ONSEMI]  52.46 91.02 90 bottom
D22  -  [ESD_2P_33_39X24_H24]  146.87 63.74 90 top
D23  -  [SOD523]  259.01 15.86 270 top
D24  -  [SOD523]  259.01 19.17 270 top
D25  -  [ESD_2P_33_39X24_H24]  146.87 61.58 270 top
D64  -  [SOD323]  18.48 126.74 0 bottom
D65  -  [SOD323]  18.48 126.74 0 top
D66  -  [SOT23_S6_FITI_H51]  81.34 145.66 270 bottom
D67  -  [ESD_2P_33_39X24_H24]  155.13 137.78 180 bottom
D68  -  [SOT23_2D4_H43]  93.86 144.44 90 top
D69  -  [ESD_2P_33_39X24_H24]  157.16 137.78 0 bottom
D2301  -  [DFN_9P_34_39X98_AMA]  14.16 116.63 180 top
D2302  -  [DFN_9P_34_39X98_AMA]  14.42 111.29 0 top
D2700  -  [SOT23_H43]  21.6 139.46 180 top
D2800  -  [SOT23_S6_FITI_H51]  169.88 119.12 90 top
D2801  -  [SOT23_S6_FITI_H51]  163.51 122.16 90 top
D7101  -  [ESD_2P_33_39X24_H20]  240.98 106.46 180 bottom
D7102  -  [ESD_2P_33_39X24_H20]  249.62 110.49 90 bottom
D7103  -  [ESD_2P_33_39X24_H20]  245.32 111.37 270 bottom
D7108  -  [ESD_2P_33_39X24_H17]  17.11 97.02 90 bottom
D7109  -  [ESD_2P_33_39X24_H17]  17.11 94.98 270 bottom
D7110  -  [SOD523]  178.22 35.1 0 bottom
D7111  -  [SOD523]  98.87 128.64 270 bottom
D7112  -  [SOD523]  98.87 125.34 270 bottom
D7113  -  [ESD_2P_33_39X24_H24]  193.61 144.39 0 top
D7117  -  [ESD_2P_33_39X24_H20]  241.92 111.37 270 bottom
D7118  -  [ESD_2P_33_39X24_H20]  240.38 103.92 180 bottom
D7119  -  [ESD_2P_33_39X24_H24]  41.06 96.84 270 bottom
D7120  -  [ESD_2P_33_39X24_H24]  39.79 96.84 270 bottom
D7121  -  [ESD_2P_33_39X24_H24]  40.96 94.73 90 top
D7122  -  [ESD_2P_33_39X24_H24]  40.96 91.68 270 top
D7123  -  [SOT323_ONSEMI]  47.76 112.61 0 bottom
FANF1  -  [POLYSWITCH_2P_179X128_POLY]  76.16 73.9 90 top
H1  -  [NB_H_C287D110_P2_S]  247.73 68.55 0 top
H2  -  [NB_H_C287D110_P2_S]  271.73 5.55 0 top
H2_2  -  [HOLE_C59D59N]  275.53 5.55 0 top
H3  -  [NB_H_C287D110_P2_S]  69.53 23.8 180 top
H3_2  -  [HOLE_C59D59N]  72.73 21.95 0 top
H5  -  [NB_H_C287D110_P2_S]  64.18 150.4 0 top
H5_2  -  [HOLE_O59X108DO59X108N]  64.18 145.97 0 top
H6  -  [NB_H_C287D110_P2_S]  140.28 143.55 0 top
H7  -  [NB_H_C287D110_P2_S]  198.23 150.4 0 top
H8  -  [NB_H_C287D110_P2_S]  178.93 115.25 0 top
H9  -  [NB_H_C287D110_P2_S]  212.28 68.05 0 top
H10  -  [NB_H_C287D110_P2_S]  5.5 140.02 0 top
H11  -  [NB_H_C287D177_P2_S]  20.5 88.3 270 top
H12  -  [NB_H_C287D110_P2_S]  177.78 23.8 0 top
H13  -  [NB_NUT_C217B176D146H264_LF2]  63.08 130.8 180 bottom
H14  -  [NB_NUT_C217B176D146H264_LF2]  57.68 127.8 180 bottom
H15  -  [NB_NUT_CT236B156D126_LF2]  65.33 106.75 180 bottom
H16  -  [NB_NUT_CT236B156D126_LF2]  25.23 106.75 0 bottom
H17  -  [NB_NUT_C236D150_H161_LF2]  161.73 69.73 180 bottom
H18  -  [NB_NUT_CT197BD126_H358_LF2]  112.03 133.18 180 bottom
H19  -  [NB_NUT_C197BD122_LF2]  134.03 133.18 180 bottom
H20  -  [NB_H_CB256D181_P2_S]  79.37 83.38 0 top
H21  -  [NB_H_CB256D181_P2_S]  145.37 103.38 0 top
H22  -  [NB_H_CB256D181_P2_S]  79.37 103.38 0 top
H23  -  [NB_H_CB256D181_P2_S]  145.37 83.38 0 top
H24  -  [HOLE_C59D59N]  167.73 69.73 0 top
H25  -  [HOLE_O335X217DO335X217N]  235.81 45.3 150 top
H7101  -  [NB_H_C217D98_P2_S]  257.41 88.85 0 top
H7102  -  [NB_H_C217D98_P2_S]  243.49 119.4 0 top
H7301  -  [NB_H_C217D91_116_P2_S]  209.99 95.4 0 top
H7302  -  [NB_H_C217D91_116_P2_S]  209.99 125.4 0 top
HDMIU1  -  [SC59_DI]  18.23 122.16 270 bottom
JAPS1  -  [NB_FPC_18P_20_2HOLD_ACE_B]  162.49 82.16 90 top
JBAT1  -  [WTOB_13P_59]  158.9 33 270 bottom
JBAT_PK1  -  [WTOB_13P_59]  209.18 110.4 270 bottom
JBAT_PK2  -  [BATT_9P_79_2HD_SUYIN_LF5]  214.13 110.4 270 bottom
JCRT1  -  [NB_D_SUB_15P_2HD_SYN_LF2]  84.38 147.53 0 bottom
JCSW1  -  [NB_FPC_6P_20_2HD_RA_ACES_B]  125.25 59.63 0 top
JCSW2  -  [WTOB_5P_49_2HOLD_RA_ACES]  173.44 126.75 90 bottom
JDCIN1  -  [WTOB_7P_59_ACE]  31.4 92.08 180 bottom
JDEG1  -  [NB_FPC_10P_20_2HOLD_RA_TE]  152.39 72.7 0 top
JDEG2  -  [FPC_12P_20_2HOD_RA_ACE_B]  140.78 73.7 0 top
JDIMM1  -  [DDR4_260P_20_4H_REV_DNT]  114.64 42.58 180 bottom
JDIMM2  -  [DDR4_260P_4HOLD_STD_DRAG]  114.64 29.28 180 bottom
JDOCK1  -  [FPC_56P_20_2HD_ACES]  160.45 89.9 270 bottom
JEDP1  -  [WTOB_50P_20_5HOLD_ACES]  45.28 103.62 0 bottom
JEPC1  -  [NB_FPC_38P_20_2HD_RA_ACES_B]  182.88 59.55 0 bottom
JFAN1  -  [WTOB_4P_49_2HD_ACE]  72.9 71.24 130 bottom
JFWP1  -  [SW_3P_98_2HD_RA_DIPTR]  190.3 121.15 90 top
JGFX1  -  [NB_BTOB_80P_20_2HOLD_F_SAM]  121.95 141.03 0 bottom
JGPS1  -  [WTOB_5P_49_2HD_RA_MOLEX]  167.01 114.9 270 bottom
JHDMI1  -  [NB_HDMI_19P_4HOLD_RA_LF2]  3.7 113.2 90 bottom
JHS1  -  [WTOB_10P_39_2HD_CLUX]  167.78 27.4 180 bottom
JIOR1  -  [FPC_56P_20_2HD_ACES]  180.98 93.48 270 bottom
JKB1  -  [NB_FPC_10P_20_2HD_RA_ACS_B]  149.55 51.63 90 top
JLAN1  -  [LAN_JACK_13P_2H_ALL_S_LF5]  172.89 151.28 0 bottom
JLED1  -  [FPC_12P_20_2HOD_RA_ACE_B]  262.43 5.4 180 bottom
JLID1  -  [NB_FPC_6P_20_2HD_RA_ACES_B]  116.55 59.63 0 top
JODD1  -  [NB_FPC_16P_20_2HOLD_RA_AC_B]  195.48 31.2 90 bottom
JPSEN1  -  [WTOB_4P_31_2HOLD_ACES]  91.14 113.47 0 bottom
JRCAM1  -  [NB_WTOB_10P_24_2HLD_AES]  207.61 148.58 180 bottom
JRTC1  -  [WTOB_2P_49_2HD_RA_TYCO]  74.89 30.89 270 bottom
JSEC1  -  [FPC_26P_39_4HOLD_CVI]  170.94 38.8 0 bottom
JSER1  -  [NB_D_SUB_9P_2HD_M_CON_LF2]  119.19 147.47 0 bottom
JSH1  -  [NB_FPC_16P_20_2HOLD_RA_AC_B]  175.93 50 270 bottom
JSIM1  -  [NB_SIM_8P_28_10HD_PLAS]  247.65 100.8 270 bottom
JSIMUAJ1  -  [FPC_18P_39_2HOLD_ACE]  16.98 139.73 180 bottom
JSIMUAJ2  -  [FPC_18P_20_2HLD_ACES]  245.71 104.4 180 top
JSPI1  -  [SOCKET_8P_50_LOTE]  157.48 114.9 180 bottom
JSPK1  -  [WTOB_4P_49_2HD_ACE]  43.38 87.9 180 bottom
JSTRG1  -  [FPC_40P_20_2HD_RA_ENTERY]  158.43 55.1 270 bottom
JTAG1  -  [NB_OPEN2_5MIL_PT]  229.93 68.95 90 top
JTP1  -  [NB_FPC_8P_20_2HD_RA_ACES_B]  140.85 58.93 0 top
JUAJ1  -  [NB_AUDIO_JACK_8P_2HOLD_RA]  256.61 116.92 270 bottom
JUSB1  -  [NB_USB_9P_4HLD_RA_FOX_LF2]  5.2 93.75 90 bottom
JUSB2  -  [NB_USB_1X4P_4H_RA_FXC_LF2]  152.28 143.8 0 bottom
JWLAN1  -  [NB_MINI_PCI_67P_20_4HD_LO]  30.23 127.77 270 bottom
JWWAN1  -  [NB_MINI_PCI_67P_20_4HD_LTS]  102.51 130.83 90 bottom
JXDP1  -  [BTOB_60P_20_F_SAM]  76.05 117.34 0 bottom
L1  -  [L0603_POLAR]  72.45 145.97 90 bottom
L2  -  [L0603_POLAR]  74.99 144.07 90 bottom
L3  -  [L0603_POLAR]  77.53 142.75 90 bottom
L4  -  [L0603]  83.75 143.23 0 bottom
L5  -  [L0603]  85.53 141.95 0 bottom
L8  -  [CHOKE_4P_79X47_FUKUI]  27.62 101.46 270 bottom
L10  -  [CHOKE_4P_79X47_FUKUI]  17.44 115.05 180 top
L13  -  [CHOKE_4P_79X47_FUKUI]  17.44 117.59 180 top
L16  -  [CHOKE_4P_79X47_FUKUI]  17.44 112.54 180 top
L19  -  [CHOKE_4P_79X47_FUKUI]  17.44 109.97 180 top
L21  -  [L0805_H41]  42.07 127.57 0 bottom
L27  -  [L0806_H39]  142.38 125.01 270 top
L37  -  [R0603_H24]  40.68 120.1 0 bottom
L40  -  [CHOKE_4P_79X47_FUKUI]  21.78 93.97 180 top
L41  -  [CHOKE_4P_79X47_FUKUI]  21.78 96.25 180 top
L42  -  [CHOKE_4P_79X47_FUKUI]  19.35 96.1 180 bottom
L44  -  [NB_R0603_H24_SMALL]  149.24 61.58 90 top
L45  -  [NB_R0603_H24_SMALL]  149.24 63.87 270 top
L57  -  [CHOKE_4P_79X47_FUKUI]  110.55 123.66 180 bottom
L75  -  [CHOKE_4P_79X47_FUKUI]  189.71 121.54 90 bottom
L76  -  [CHOKE_4P_79X47_FUKUI_H39]  156.12 135.19 90 bottom
L77  -  [NB_L0603_H37_SMALL]  90.97 124.96 180 bottom
L78  -  [NB_L0603_H37_SMALL]  91.63 127.53 90 bottom
L79  -  [NB_L0603_H37_SMALL]  82.18 128.79 270 bottom
L80  -  [NB_L0603_H37_SMALL]  81.42 130.93 180 bottom
L2701  -  [NB_R0603_H24_SMALL]  36.69 96.89 0 top
L2702  -  [NB_R0603_H24_SMALL]  36.67 95.24 0 top
L2800  -  [TRANS_24P_50_650X370]  172.02 129.73 0 top
L3101  -  [CHOKE_4P_79X47_FUKUI]  21.39 134.18 0 bottom
L3601  -  [CHOKE_4P_79X47_FUKUI]  206.97 145.81 90 top
L3602  -  [CHOKE_4P_79X47_FUKUI]  180.15 42.21 270 bottom
L7101  -  [NB_L0402_H22_SMALL]  247.43 110.5 270 bottom
L7102  -  [NB_L0402_H22_SMALL]  243.17 111.36 90 bottom
L7103  -  [CHOKE_4P_79X47_FUKUI]  184.34 53.71 90 bottom
L7104  -  [CHOKE_4P_79X47_FUKUI]  168.09 88.63 270 bottom
L7105  -  [CHOKE_4P_79X47_FUKUI]  168.09 93.46 270 bottom
L7106  -  [CHOKE_4P_79X47_FUKUI]  168.21 83.68 270 bottom
L7107  -  [NB_L0603_H37_SMALL]  86.68 137.55 0 bottom
L7108  -  [NB_L0603_H37_SMALL]  92.39 140.96 180 bottom
LE1  -  [NB_L0402_H22_SMALL]  50.86 98.79 270 bottom
ME1  -  [NB_OPEN2_5MIL_PT]  139.58 64.2 270 bottom
NOREF  -  [unnamed]  282.15 -6.92 270 top
NOREF#2  -  [#2]  252.79 94.1 0 top
NOREF#3  -  [#2]  208.27 121.5 90 top
NOREF#4  -  [unnamed#3]  199.88 145.28 0 top
NOREF#5  -  [#2]  75.93 -51.52 0 top
NOREF#6  -  [#2]  157.3 60.75 0 top
NOREF#7  -  [unnamed]  110.62 149.32 0 top
NOREF#8  -  [#2]  181.04 41.55 0 top
NOREF#9  -  [unnamed]  145.48 141.85 0 top
NOREF#10  -  [unnamed]  134.96 149.82 0 top
NOREF#11  -  [unnamed]  -7.72 166.99 270 top
NOREF#12  -  [unnamed]  99.98 149.53 0 top
NOREF#13  -  [unnamed]  127.76 149.32 0 top
NOREF#14  -  [unnamed]  164.39 143.65 0 top
NOREF#15  -  [unnamed]  11.15 100.5 0 top
NOREF#16  -  [unnamed]  282.15 166.99 270 top
NOREF#17  -  [#2]  108.47 60.16 0 top
NOREF#18  -  [unnamed]  8.05 105.45 0 top
NOREF#19  -  [unnamed#3]  17.01 133.55 0 top
NOREF#20  -  [#2]  210.96 116.78 90 top
NOREF#21  -  [unnamed#3]  273.26 -6.92 270 top
NOREF#22  -  [unnamed]  181.39 143.65 0 top
NOREF#23  -  [unnamed]  68.78 149.53 0 top
NOREF#24  -  [#2]  260.54 105.93 0 top
NOREF#25  -  [unnamed#3]  255.48 166.99 270 top
NOREF#26  -  [#2]  168.89 40.81 0 top
NOREF#27  -  [#2]  206.49 -5.65 0 top
NOREF#28  -  [unnamed]  92.78 149.53 0 top
NOREF#29  -  [unnamed]  13.58 135.42 0 top
NOREF#30  -  [unnamed#3]  61.02 -6.92 270 top
NOREF#31  -  [unnamed]  8.05 120.95 0 top
NOREF#32  -  [unnamed]  75.98 149.53 0 top
NOREF#33  -  [unnamed]  103.42 149.82 0 top
NOREF#34  -  [#2]  205.8 98.52 90 top
NOREF#35  -  [#2]  114.48 167.54 270 top
NOREF#36  -  [#2]  259.52 99.68 0 top
NOREF#37  -  [#2]  205.05 121.49 90 top
NOREF#38  -  [unnamed#3]  259.27 2.78 0 top
NOREF#39  -  [unnamed]  11.15 87 0 top
NOREF#40  -  [unnamed]  159.08 141.85 0 top
NOREF#41  -  [unnamed]  -7.72 -6.92 270 top
NOREF#42  -  [unnamed#3]  18.95 166.99 270 top
NOREF#43  -  [#2]  46.47 165.72 0 top
NOREF#44  -  [unnamed]  13.58 124.92 0 top
NOREF#45  -  [unnamed#3]  1.17 -6.92 270 top
NOREF#46  -  [#2]  254.79 108.02 0 top
NOREF#47  -  [unnamed#3]  213.42 166.99 270 top
NOREF#48  -  [#2]  101.58 60.16 0 top
NOREF#49  -  [#2]  259.06 93.98 0 top
NOREF#50  -  [#2]  114.48 167.54 90 bottom
NOREF#51  -  [#2]  59.17 -5.65 0 bottom
NOREF#52  -  [unnamed#3]  61.02 166.99 90 bottom
NOREF#53  -  [unnamed#3]  24.03 166.99 90 bottom
NOREF#54  -  [unnamed#3]  179.67 135.55 180 bottom
NOREF#55  -  [unnamed#3]  250.4 166.99 270 bottom
NOREF#56  -  [#2]  214.94 165.72 0 bottom
NOREF#57  -  [unnamed#3]  268.18 -6.92 90 bottom
NOREF#58  -  [unnamed#3]  17.13 133.24 180 bottom
NOREF#59  -  [#2]  205.48 125.57 270 bottom
NOREF#60  -  [unnamed#3]  6.25 -6.92 90 bottom
NOREF#61  -  [unnamed#3]  213.42 -6.92 90 bottom
NOREF#62  -  [unnamed#3]  269.58 13.58 180 bottom
OCS4801  -  [OSC_4P_126X98_ECERA_H45]  264.6 42.53 0 top
PC5101  -  [NB_C0603_H34_SMALL]  152.46 29.96 90 top
PC5102  -  [NB_C0402_SMALL]  154.21 31.38 180 top
PC5103  -  [NB_C0603_H34_SMALL]  26.73 89.27 180 top
PC5104  -  [NB_C0402_SMALL]  27.33 98.16 0 bottom
PC5105  -  [NB_C0603_H34_SMALL]  34.61 88.76 0 top
PC5106  -  [NB_C0603_H34_SMALL]  34.61 87.49 0 top
PC5107  -  [NB_C0603_H34_SMALL]  68.77 74.92 180 top
PC5108  -  [NB_C0805_H55_SMALL]  68.51 76.44 180 top
PC5109  -  [NB_C0603_H34_SMALL]  68.21 87.75 180 top
PC5201  -  [NB_C0603_H35_SMALL]  235.01 27.93 270 top
PC5202  -  [NB_C0402_H22_SMALL]  234.76 29.58 180 top
PC5203  -  [NB_C0402_H22_SMALL]  233.36 28.31 270 top
PC5204  -  [NB_C0805_H55_SMALL]  227.77 36.69 90 top
PC5205  -  [NB_C0805_H55_SMALL]  224.22 36.69 90 top
PC5206  -  [NB_C0805_H55_SMALL]  225.99 36.69 90 top
PC5207  -  [NB_C0805_H55_SMALL]  218.07 30.6 270 top
PC5208  -  [NB_C0805_H55_SMALL]  216.29 30.6 270 top
PC5209  -  [C3528_H79]  213.55 28.06 90 top
PC5210  -  [NB_C0402_SMALL]  215.58 36.69 90 top
PC5211  -  [NB_C0805_H55_SMALL]  219.85 30.6 270 top
PC5212  -  [C3528_H79]  217.87 37.33 270 top
PC5213  -  [C3528_H79]  221.55 37.33 270 top
PC5214  -  [NB_C0402_H22_SMALL]  238.8 29.12 270 top
PC5215  -  [NB_C0805_H55_SMALL]  183.45 37.71 90 top
PC5216  -  [NB_C0805_H55_SMALL]  194.37 29.07 270 top
PC5217  -  [NB_C0805_H55_SMALL]  185.23 37.71 90 top
PC5218  -  [NB_C0805_H55_SMALL]  192.59 29.07 270 top
PC5219  -  [NB_C0805_H55_SMALL]  187.01 37.71 90 top
PC5220  -  [NB_C0805_H55_SMALL]  190.82 29.07 270 top
PC5221  -  [NB_C0805_H55_SMALL]  181.67 37.71 90 top
PC5222  -  [NB_C0402_SMALL]  240.85 30.6 180 top
PC5223  -  [NB_C0805_H55_SMALL]  196.15 29.07 270 top
PC5224  -  [NB_C0402_SMALL]  240.85 31.48 180 top
PC5225  -  [NB_C0603_H35_SMALL]  232.22 30.09 180 top
PC5226  -  [NB_C0603_H34_SMALL]  232.22 31.48 180 top
PC5227  -  [NB_C0603_H35_SMALL]  232.22 34.53 180 top
PC5228  -  [C0805_H57]  169.36 23.99 270 top
PC5229  -  [C0805_H57]  171.44 23.99 270 top
PC5230  -  [C0805_H57]  169.63 31.74 90 top
PC5231  -  [C0805_H57]  171.79 31.74 90 top
PC5232  -  [NB_C0402_H22_SMALL]  236.28 36.44 0 top
PC5233  -  [NB_C0603_H34_SMALL]  209.48 39.36 0 top
PC5234  -  [NB_C0402_SMALL]  240.85 34.41 180 top
PC5235  -  [NB_C0402_H22_SMALL]  235.39 37.33 180 top
PC5236  -  [NB_C0402_H22_SMALL]  236.66 37.71 90 top
PC5237  -  [NB_C0402_SMALL]  240.85 35.68 180 top
PC5238  -  [NB_C0402_SMALL]  232.85 35.93 90 top
PC5239  -  [NB_C0603_H35_SMALL]  238.19 36.56 0 top
PC5240  -  [NB_C0402_SMALL]  224.01 45.28 270 top
PC5241  -  [NB_C0402_SMALL]  224.01 43.12 270 top
PC5301  -  [NB_C0603_H39_SMALL]  185.1 64.55 0 top
PC5302  -  [NB_C0603_H39_SMALL]  185.1 65.77 0 top
PC5303  -  [NB_C0402_SMALL]  185.1 66.79 0 top
PC5304  -  [NB_C0603_H34_SMALL]  200.42 62.9 0 top
PC5305  -  [NB_C0603_H34_SMALL]  200.42 61.7 0 top
PC5306  -  [NB_C0603_H39_SMALL]  185.61 56.25 180 top
PC5307  -  [NB_C0603_H39_SMALL]  185.61 57.52 180 top
PC5308  -  [NB_C0402_SMALL]  186.5 54.85 270 top
PC5309  -  [NB_C0402_SMALL]  187.26 54.85 270 top
PC5310  -  [NB_C0603_H34_SMALL]  195.01 66.92 270 top
PC5311  -  [NB_C0603_H34_SMALL]  195.51 59.17 270 top
PC5312  -  [C7343]  176.85 73.65 0 bottom
PC5313  -  [C7343]  198.31 48.25 0 top
PC5314  -  [NB_C0603_H35_SMALL]  189.93 69.97 270 top
PC5315  -  [NB_C0603_H35_SMALL]  189.55 49.77 90 top
PC5316  -  [NB_C0402_SMALL]  193.48 69.08 180 top
PC5317  -  [NB_C0402_SMALL]  189.93 63.11 270 top
PC5318  -  [NB_C0603_H34_SMALL]  191.2 64.63 180 top
PC5319  -  [NB_C0402_SMALL]  193.61 60.72 180 top
PC5320  -  [NB_C0603_H39_SMALL]  185.61 58.79 180 top
PC5321  -  [NB_C0603_H39_SMALL]  185.1 63.34 0 top
PC5401  -  [NB_C0805_H55_SMALL]  82.71 58.54 270 top
PC5402  -  [NB_C0805_H55_SMALL]  80.96 58.54 270 top
PC5403  -  [NB_C0402_SMALL]  84.39 59.55 0 top
PC5404  -  [NB_C0402_SMALL]  84.39 58.69 0 top
PC5405  -  [NB_C0603_H34_SMALL]  82.54 50.15 270 top
PC5406  -  [NB_C0805_H55_SMALL]  89.72 51.68 90 top
PC5407  -  [NB_C0805_H55_SMALL]  91.45 49.9 270 top
PC5408  -  [NB_C0603_H34_SMALL]  81.9 52.97 90 top
PC5409  -  [NB_C0603_H34_SMALL]  81.9 55.26 90 top
PC5410  -  [C7343_H63]  90.36 64.76 90 top
PC5411  -  [NB_C0603_H34_SMALL]  88.5 53.73 0 top
PC5412  -  [NB_C0603_H35_SMALL]  79.31 74.41 90 top
PC5413  -  [NB_C0402_SMALL]  88.68 55.53 90 top
PC5414  -  [NB_C0402_SMALL]  89.93 54.95 0 top
PC5415  -  [NB_C0402_SMALL]  84.82 55.77 180 top
PC5416  -  [NB_C0603_H39_SMALL]  86.17 49.14 270 top
PC5501  -  [NB_C0805_H55_SMALL]  135.68 125.46 270 bottom
PC5502  -  [NB_C0603_H34_SMALL]  131.81 129.22 0 top
PC5503  -  [NB_C0805_H55_SMALL]  136.33 129.02 90 top
PC5504  -  [NB_C0402_SMALL]  138.15 125.85 270 top
PC5505  -  [NB_C0402_SMALL]  137.32 125.85 270 top
PC5506  -  [NB_C0402_SMALL]  130.36 127.75 270 top
PC5507  -  [C0603]  138.19 116.22 270 bottom
PC5508  -  [C0603]  141.41 116.96 270 top
PC5509  -  [NB_C0603_H39_SMALL]  138.14 116.14 270 top
PC5510  -  [NB_C0603_H39_SMALL]  140.14 119.11 0 bottom
PC5511  -  [NB_C0603_H35_SMALL]  137.86 123.43 90 top
PC5512  -  [NB_C0603_H34_SMALL]  132.29 127.24 90 top
PC5513  -  [NB_C0603_H34_SMALL]  134.81 128.87 90 top
PC5514  -  [NB_C0402_SMALL]  132.47 122.8 90 top
PC5601  -  [NB_C0402_SMALL]  175.7 78.4 180 bottom
PC5602  -  [NB_C0402_SMALL]  170.04 75.71 180 bottom
PC5603  -  [NB_C0402_SMALL]  170.04 74.87 180 bottom
PC5604  -  [NB_C0603_H39_SMALL]  168.01 73.11 90 bottom
PC5605  -  [NB_C0603_H39_SMALL]  169.73 73.85 180 bottom
PC5606  -  [NB_C0603_H39_SMALL]  174.99 86.86 0 bottom
PC5607  -  [NB_C0603_H39_SMALL]  174.99 88.13 0 bottom
PC5608  -  [NB_C0603_H39_SMALL]  174.99 85.59 0 bottom
PC5609  -  [NB_C0402_SMALL]  168.21 79.44 90 bottom
PC5610  -  [NB_C0402_SMALL]  167.83 76.44 180 bottom
PC5611  -  [NB_C0402_SMALL]  167.57 101.56 90 bottom
PC5612  -  [NB_C0402_SMALL]  171.03 104.86 180 bottom
PC5613  -  [NB_C0603_H39_SMALL]  175.45 95.87 0 bottom
PC5614  -  [NB_C0603_H39_SMALL]  170.62 94.1 270 bottom
PC5615  -  [NB_C0402_SMALL]  173.8 104.89 0 bottom
PC5616  -  [NB_C0603_H39_SMALL]  170.75 107.58 180 bottom
PC5617  -  [NB_C0603_H39_SMALL]  175.45 97.14 0 bottom
PC5618  -  [NB_C0603_H39_SMALL]  170.75 106.31 180 bottom
PC5619  -  [NB_C0402_SMALL]  175.45 100.83 0 bottom
PC5620  -  [NB_C0402_SMALL]  175.45 103.42 0 bottom
PC5701  -  [NB_C0402_SMALL]  213.04 58.79 270 top
PC5702  -  [NB_C0603_H39_SMALL]  210.45 59.6 270 top
PC5703  -  [NB_C0603_H39_SMALL]  211.75 59.73 270 top
PC5704  -  [NB_C0402_SMALL]  218.91 63.72 90 top
PC5705  -  [NB_C0603_H39_SMALL]  219.52 58.79 0 top
PC5706  -  [NB_C0402_SMALL]  219.26 56.5 0 top
PC5707  -  [NB_C0603_H39_SMALL]  219.52 57.52 0 top
PC5708  -  [NB_C0402_SMALL]  216.27 64.94 90 top
PC5709  -  [NB_C0603_H35_SMALL]  214.56 58.92 180 top
PC5710  -  [NB_C0402_SMALL]  188.45 107 180 top
PC5711  -  [NB_C0603_H39_SMALL]  190.56 106.8 0 top
PC5712  -  [NB_C0603_H39_SMALL]  188.35 105.93 180 top
PC5713  -  [NB_C0603_H39_SMALL]  187.64 114.92 90 top
PC5714  -  [NB_C0603_H39_SMALL]  188.91 114.92 90 top
PC5715  -  [NB_C0402_SMALL]  187.26 112.51 270 top
PC5716  -  [NB_C0402_SMALL]  186.73 110.25 90 top
PC5717  -  [NB_C0402_SMALL]  184.95 108.22 90 top
PC5718  -  [NB_C0603_H35_SMALL]  190.94 109.34 270 top
PC5719  -  [NB_C0402_SMALL]  212.35 53.15 180 top
PC5720  -  [NB_C0603_H39_SMALL]  212.28 50.86 180 top
PC5721  -  [NB_C0603_H39_SMALL]  212.28 52.11 180 top
PC5722  -  [NB_C0402_SMALL]  214.44 54.98 180 top
PC5723  -  [NB_C0603_H39_SMALL]  219.52 51.04 0 top
PC5724  -  [NB_C0603_H39_SMALL]  219.52 49.77 0 top
PC5725  -  [NB_C0603_H39_SMALL]  66.94 131.84 180 top
PC5726  -  [NB_C0402_SMALL]  66.74 138.04 180 top
PC5727  -  [NB_C0402_SMALL]  219.26 48.63 0 top
PC5728  -  [NB_C0603_H35_SMALL]  214.51 50.79 180 top
PC5729  -  [NB_C0402_SMALL]  212.28 55.61 180 top
PC5730  -  [NB_C0603_H35_SMALL]  68.77 140.83 90 top
PC5731  -  [NB_C0402_SMALL]  70.47 133.98 180 top
PC5732  -  [NB_C0603_H39_SMALL]  70.89 136.21 180 top
PC5733  -  [NB_C0402_SMALL]  66.23 134.48 270 top
PC5734  -  [NB_C0603_H39_SMALL]  70.89 134.99 180 top
PC5735  -  [NB_C0402_SMALL]  66.74 132.86 180 top
PC5736  -  [NB_C0603_H39_SMALL]  66.94 130.61 180 top
PC5737  -  [NB_C0603_H39_SMALL]  68.87 133.87 90 bottom
PC5738  -  [NB_C0603_H39_SMALL]  70.14 133.87 90 bottom
PC5739  -  [NB_C0603_H39_SMALL]  66.94 129.36 180 top
PC5801  -  [NB_C0402_SMALL]  65.34 120 90 top
PC5802  -  [NB_C0402_SMALL]  69.99 125.29 180 top
PC5803  -  [NB_C0603_H35_SMALL]  72.93 120.41 270 top
PC5804  -  [NB_C0402_SMALL]  75.12 120.13 270 top
PC5805  -  [NB_C0402_SMALL]  67.57 115.43 180 top
PC5806  -  [NB_C0402_SMALL]  77.46 115.26 90 top
PC5807  -  [NB_C0402_SMALL]  77.89 118.12 0 top
PC5808  -  [NB_C0402_SMALL]  63.28 116.96 180 top
PC5809  -  [NB_C0402_SMALL]  80.58 116.07 180 top
PC5810  -  [NB_C0402_SMALL]  77.89 117.3 0 top
PC5812  -  [NB_C0402_SMALL]  76.85 112.66 180 top
PC5813  -  [NB_C0402_SMALL]  62.52 112 0 top
PC5814  -  [NB_C0402_SMALL]  65.19 113.83 0 top
PC5815  -  [NB_C0402_SMALL]  76.67 111.75 180 top
PC5816  -  [NB_C0402_SMALL]  79.11 113.58 0 top
PC5817  -  [NB_C0402_SMALL]  83.07 112.59 180 top
PC5818  -  [NB_C0402_SMALL]  84.79 109.82 0 top
PC5819  -  [NB_C0402_SMALL]  83.07 110.07 0 top
PC5820  -  [NB_C0402_SMALL]  67.22 113.6 0 top
PC5821  -  [NB_C0402_SMALL]  65.19 112.99 0 top
PC5822  -  [NB_C0402_SMALL]  62.52 112.89 180 top
PC5823  -  [NB_C0402_SMALL]  80.13 110.5 90 top
PC5824  -  [NB_C0402_SMALL]  83.07 110.91 0 top
PC5825  -  [NB_C0402_SMALL]  76.85 113.7 180 top
PC5826  -  [NB_C0402_SMALL]  78.29 109.84 270 top
PC5827  -  [NB_C0402_SMALL]  76.9 109.84 270 top
PC5828  -  [NB_C0402_SMALL]  67.93 109.26 270 top
PC5830  -  [NB_C0402_SMALL]  76.01 109.84 270 top
PC5831  -  [NB_C0402_SMALL]  67.07 112.61 0 top
PC5832  -  [NB_C0402_SMALL]  67.07 111.79 0 top
PC5834  -  [NB_C0402_SMALL]  67.19 110.78 180 top
PC5835  -  [NB_C0402_SMALL]  69.05 108.79 270 top
PC5836  -  [NB_C0402_SMALL]  70.72 108.79 90 top
PC5837  -  [NB_C0402_SMALL]  72.91 105.02 90 top
PC5838  -  [NB_C0402_SMALL]  72.07 106.92 270 top
PC5839  -  [NB_C0402_SMALL]  64.86 111.11 0 top
PC5840  -  [NB_C0402_SMALL]  72.91 106.92 90 top
PC5841  -  [NB_C0402_SMALL]  72.07 108.83 270 top
